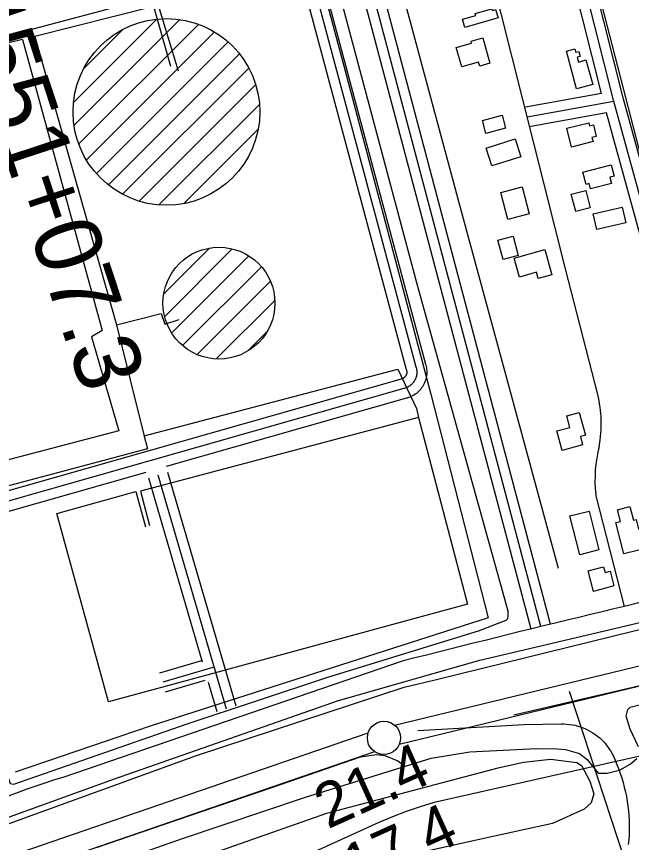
# Model space of a CAD drawing. Extents: x 3508733 to 3546731, y 546897 to 572481.
# Drawn here: x 3515132 to 3516057, y 565615 to 566859 of the extents above; entities that cross this region are included whole.
import ezdxf

# ---------------------------------------------------------------- set-up
doc = ezdxf.new("R2010")
doc.units = 0
for name, color, linetype in [('V-BLDG-OTLN', 7, 'Continuous'), ('V-DOMW-TANK', 7, 'Continuous'), ('V-FLOD-BASE', 7, 'Continuous'), ('V-LEVE-TOET', 7, 'Continuous'), ('V-RIVR-RANG', 7, 'Continuous'), ('V-ROAD-CNTR', 7, 'Continuous'), ('V-SITE-OTLN', 7, 'Continuous'), ('V-SITE-VEGE', 7, 'Continuous'), ('V-SURV-IDEN', 7, 'Continuous'), ('V-SURV-LINE', 7, 'Continuous'), ('V-TOPO-MINR', 7, 'Continuous'), ('V-TOPO-SHOR', 7, 'Continuous'), ('V-UTIL-LINE', 7, 'Continuous')]:
    doc.layers.add(name, color=color, linetype=linetype)

msp = doc.modelspace()

# ---------------------------------------------------------------- linework, layer by layer
at = {"layer": 'V-BLDG-OTLN'}
for points in [[(3515856, 566856.5), (3515806.2, 566842.1), (3515802.6, 566854.4), (3515822.5, 566860.2), (3515821.7, 566863), (3515846.5, 566870.2), (3515847.3, 566867.5), (3515852.4, 566869)], [(3515833, 566826.5), (3515843.8, 566788.4), (3515828.4, 566784), (3515826.7, 566790.1), (3515801.4, 566782.9), (3515793.1, 566812.1), (3515816.3, 566818.7), (3515815.5, 566821.5)], [(3515988.3, 566793.2), (3515998.4, 566756.3), (3515974.2, 566749.7), (3515958.8, 566806.3), (3515971.5, 566809.7), (3515972.9, 566804.7), (3515977.3, 566805.9), (3515979.3, 566798.4), (3515975, 566797.2), (3515976.9, 566790.1)], [(3515867.2, 566690.3), (3515837.8, 566682.6), (3515832.7, 566702.3), (3515862.1, 566709.9)], [(3515998.9, 566670.2), (3515966.3, 566662.1), (3515959.3, 566690.4), (3515992.6, 566698.6), (3515993.7, 566694.2), (3515999.5, 566695.6), (3516003.8, 566678), (3515997.3, 566676.4)], [(3515890.3, 566647.6), (3515846.7, 566633.6), (3515838.1, 566660.4), (3515881.6, 566674.4)], [(3515983.8, 566624.5), (3516026.2, 566635.4), (3516030.5, 566618.5), (3516024.1, 566616.8), (3516026.7, 566607), (3515995.2, 566599), (3515993.1, 566607), (3515988.6, 566605.9)], [(3515892.5, 566602), (3515902.9, 566561.5), (3515870.7, 566553.2), (3515860.3, 566593.6)], [(3515994.7, 566570.7), (3515972.8, 566565.1), (3515966.1, 566591), (3515988.1, 566596.7)], [(3516048.3, 566548.2), (3516004.8, 566538.1), (3515999.3, 566561.6), (3516042.9, 566571.7)], [(3515863.5, 566492.6), (3515855.7, 566522), (3515878.6, 566528.1), (3515886.4, 566498.7)], [(3515880.5, 566495), (3515926.5, 566507.8), (3515937.1, 566469.9), (3515916.5, 566464.1), (3515913.9, 566473.5), (3515888.5, 566466.4)], [(3515983.2, 566213.7), (3515952.6, 566205.3), (3515944.5, 566234.7), (3515964.2, 566240.1), (3515959.5, 566257.3), (3515978.1, 566262.4), (3515987.5, 566228.3), (3515979.8, 566226.2)], [(3515979.1, 566048.2), (3515964.2, 566106.7), (3515992.9, 566114), (3516007.8, 566055.5)], [(3516088.1, 566060.3), (3516045, 566049.5), (3516033.1, 566096.7), (3516040.1, 566098.4), (3516035.6, 566116.2), (3516054.5, 566121), (3516059.7, 566100.6), (3516063.8, 566101.6), (3516067.5, 566086.9), (3516080.6, 566090.2)], [(3516030.4, 566001.3), (3515999.8, 565993.2), (3515991.6, 566024.1), (3516014.8, 566030.3), (3516017.3, 566021.5), (3516024.6, 566023.4)]]:
    msp.add_lwpolyline(points, close=True, dxfattribs=at)
at = {"layer": 'V-DOMW-TANK'}
for p, q in [((3515217.7, 566729.7), (3515342.5, 566854.5)), ((3515218.3, 566695), (3515377.2, 566853.9)), ((3515225.5, 566666.8), (3515405.4, 566846.7)), ((3515233.3, 566780.7), (3515291.5, 566838.9)), ((3515236.8, 566642.7), (3515429.4, 566835.4)), ((3515251.8, 566622.4), (3515449.8, 566820.4)), ((3515269.8, 566605), (3515467.1, 566802.3)), ((3515291.3, 566591.2), (3515481, 566780.9)), ((3515316.2, 566580.8), (3515491.5, 566756)), ((3515345.7, 566574.9), (3515497, 566726.2)), ((3515383.2, 566577.1), (3515495.1, 566688.9)), ((3515353.5, 566441.2), (3515422, 566509.8)), ((3515354.6, 566407), (3515456.3, 566508.8)), ((3515365.2, 566382.3), (3515481.1, 566498.1)), ((3515381.6, 566363.3), (3515500.1, 566481.8)), ((3515403.5, 566349.8), (3515513.6, 566460)), ((3515432.1, 566343.1), (3515520, 566431)), ((3515479.6, 566355.2), (3515508.3, 566384))]:
    msp.add_line(p, q, dxfattribs=at)
for centre, radius in [((3515357.2, 566715), 140.5), ((3515436.2, 566427.1), 84.2)]:
    msp.add_circle(centre, radius, dxfattribs=at)
at = {"layer": 'V-FLOD-BASE'}
for points in [[(3515879.8, 565807.3), (3516153.3, 565871.3)], [(3515251.9, 565607.5), (3515370.1, 565648.2), (3515515.9, 565698), (3515649.3, 565744.1), (3515673.4, 565747.8), (3515685.8, 565746.1), (3515705.3, 565737.9), (3515710, 565734.4)]]:
    msp.add_lwpolyline(points, dxfattribs=at)
at = {"layer": 'V-LEVE-TOET'}
for points in [[(3514850.8, 565476.6), (3514903.4, 565510.7), (3515017.6, 565594.7), (3515041.7, 565614.3), (3515064, 565624.5), (3515103.4, 565637.7), (3515402.4, 565746.1), (3515714.9, 565848.8), (3515765.6, 565860.9), (3516060.6, 565934), (3516227.3, 565973.3), (3516431, 566026.4), (3516563, 566047.8)], [(3516067.1, 565759.4), (3516054.6, 565785.8), (3516048.6, 565805.2), (3516051.4, 565815.2), (3516055, 565818.8), (3516177.2, 565848.9)], [(3515263.9, 565580), (3515381.3, 565621.3), (3515566.3, 565683.5), (3515755.4, 565742.3), (3515813.5, 565751.5), (3515914.1, 565756.8), (3515945.3, 565756.4), (3515957.7, 565755.2), (3515978.3, 565748.9), (3515990.1, 565740.1), (3516006.7, 565719.6), (3516020.2, 565719.7), (3516038.1, 565724.2), (3516039.6, 565724.5), (3516054.9, 565732.9), (3516064.8, 565741.8)]]:
    msp.add_lwpolyline(points, dxfattribs=at)
at = {"layer": 'V-RIVR-RANG'}
msp.add_line((3515963.1, 565843.1), (3516255.8, 564949.8), dxfattribs=at)
at = {"layer": 'V-ROAD-CNTR'}
msp.add_line((3515735.5, 565783.6), (3515895.1, 565792.8), dxfattribs=at)
for points in [[(3516119.9, 566404), (3516029.5, 566732.6), (3515737.3, 567893)], [(3516134.4, 566407.9), (3516044, 566736.4), (3515751.8, 567896.6)], [(3516011.6, 566742.5), (3515722.7, 567889.3)], [(3515342.9, 567842.8), (3515468.4, 567376.2), (3515746.9, 566335.2)], [(3516006, 566289.8), (3515957.6, 566478.6), (3515637, 567752), (3515609.3, 567843.5)], [(3515328.4, 567838.9), (3515453.9, 567372.3), (3515732.4, 566331.3)], [(3515906, 565936.3), (3515404.9, 567828.5)], [(3515920.5, 565940.2), (3515419.4, 567832.3)], [(3515935, 565944), (3515433.9, 567836.2)], [(3515443.6, 567352.8), (3515718, 566327.4)], [(3516011.6, 566742.5), (3515897.4, 566722)], [(3516030.1, 566730.6), (3515900, 566707.3)], [(3516019.2, 566713.4), (3515902.7, 566692.5)], [(3516105.4, 566400), (3516019.2, 566713.4)], [(3515718.1, 566326.9), (3515718.4, 566325.9), (3515718.5, 566325.4), (3515718.6, 566324.8), (3515718.7, 566324.2), (3515718.8, 566323.6), (3515718.8, 566323), (3515718.7, 566322.5), (3515718.7, 566321.9), (3515718.6, 566321.3), (3515718.5, 566320.7), (3515718.3, 566320.2), (3515718.1, 566319.6), (3515717.9, 566319.1), (3515717.7, 566318.5), (3515717.4, 566318), (3515717.1, 566317.5), (3515716.8, 566317), (3515716.4, 566316.6), (3515716, 566316.1), (3515715.6, 566315.7), (3515715.2, 566315.3), (3515714.8, 566315), (3515714.3, 566314.6), (3515713.8, 566314.3), (3515713.3, 566314), (3515712.8, 566313.7), (3515712.2, 566313.5), (3515711.7, 566313.3), (3515711.1, 566313.1), (3515710.5, 566313)], [(3515732.4, 566331.3), (3515732.9, 566329.9), (3515733.2, 566328.5), (3515733.5, 566327.1), (3515733.6, 566325.7), (3515733.7, 566324.3), (3515733.8, 566322.9), (3515733.7, 566321.4), (3515733.6, 566320), (3515733.4, 566318.6), (3515733.1, 566317.2), (3515732.7, 566315.8), (3515732.3, 566314.5), (3515731.7, 566313.2), (3515731.1, 566311.9), (3515730.5, 566310.6), (3515729.7, 566309.4), (3515728.9, 566308.2), (3515728, 566307.1), (3515727.1, 566306), (3515726.1, 566305), (3515725.1, 566304), (3515724, 566303.1), (3515722.8, 566302.3), (3515721.6, 566301.5), (3515720.4, 566300.8), (3515719.1, 566300.1), (3515717.8, 566299.6), (3515716.5, 566299.1), (3515715.1, 566298.7), (3515714.2, 566298.4)], [(3515746.8, 566335.7), (3515747.3, 566333.9), (3515747.9, 566331.7), (3515748.3, 566329.5), (3515748.6, 566327.2), (3515748.7, 566325), (3515748.8, 566322.7), (3515748.7, 566320.4), (3515748.5, 566318.2), (3515748.1, 566315.9), (3515747.7, 566313.7), (3515747.1, 566311.5), (3515746.4, 566309.4), (3515745.5, 566307.3), (3515744.6, 566305.2), (3515743.5, 566303.2), (3515742.3, 566301.3), (3515741.1, 566299.4), (3515739.7, 566297.6), (3515738.2, 566295.9), (3515736.6, 566294.3), (3515734.9, 566292.7), (3515733.2, 566291.3), (3515731.4, 566289.9), (3515729.5, 566288.7), (3515727.5, 566287.6), (3515725.5, 566286.5), (3515723.4, 566285.6), (3515721.3, 566284.9), (3515719.2, 566284.2), (3515717.9, 566283.9)], [(3515710.1, 566312.9), (3514859.2, 566070.6), (3514514.1, 565975.8)], [(3515714.2, 566298.4), (3514863.3, 566056.1), (3514503.5, 565957.3), (3514615.1, 565518.5)], [(3515718.3, 566284), (3515356.8, 566181.1)], [(3515326.2, 566172.3), (3514885.1, 566046.8)], [(3515330.1, 566164.2), (3515411, 565887.3)], [(3515344.5, 566168.4), (3515447.2, 565816.5)], [(3515358.9, 566172.6), (3515461.6, 565820.7)], [(3516046.1, 565970.5), (3516003.1, 566139.1)], [(3515347.4, 565870.7), (3515410.3, 565889.2)], [(3515713.2, 565888.4), (3515201.1, 565712.9)], [(3515426.8, 565878.4), (3515351.7, 565856.3)], [(3515355.9, 565841.9), (3515415.6, 565859.4)], [(3515419.9, 565856.6), (3515432.8, 565812.3)], [(3515895.1, 565792.8), (3515951, 565793.7), (3515955.2, 565793.7), (3515959.4, 565793.5), (3515963.6, 565793), (3515967.8, 565792.4), (3515971.9, 565791.6), (3515975.9, 565790.5), (3515980, 565789.3), (3515983.9, 565787.8), (3515987.8, 565786.2), (3515991.6, 565784.4), (3515995.3, 565782.3), (3515998.8, 565780.1), (3516002.3, 565777.8), (3516005.7, 565775.2), (3516008.9, 565772.5), (3516012, 565769.7), (3516014.9, 565766.6), (3516017.7, 565763.5), (3516020.3, 565760.2), (3516022.7, 565756.8), (3516025, 565753.3), (3516027.1, 565749.6), (3516029, 565745.9), (3516032, 565739.3), (3516034.8, 565732.7), (3516038.1, 565724.2), (3516039.9, 565719.1), (3516042.1, 565712.3), (3516044.1, 565705.3), (3516045.9, 565698.4), (3516047.6, 565691.3), (3516049, 565684.3), (3516050.2, 565677.1), (3516051.2, 565670), (3516052, 565662.8), (3516052.6, 565655.6), (3516053, 565648.4), (3516053.2, 565641.2), (3516053.2, 565634), (3516053, 565626.8), (3516052.5, 565619.6), (3516051.9, 565612.4)]]:
    msp.add_lwpolyline(points, dxfattribs=at)
for centre, radius, start, end in [((3515817.4, 566245.2), 193.8, 350.0559, 13.3321), ((3516196.1, 566161.9), 194.3, 165.1624, 186.7292), ((3521341, 543799), 22795.1, 102.83341, 104.29325), ((3515450.5, 564860), 888.6, 106.2989, 120.8986)]:
    msp.add_arc(centre, radius, start, end, dxfattribs=at)
at = {"layer": 'V-SITE-OTLN'}
for p, q in [((3515507.4, 567218.7), (3515625.9, 566776.8)), ((3515625.9, 566776.8), (3515754.7, 566290.2)), ((3515754.7, 566290.2), (3515841.4, 565953.5)), ((3515841.4, 565953.5), (3515332.7, 565790.4)), ((3515332.7, 565790.4), (3515129.4, 565720.9))]:
    msp.add_line(p, q, dxfattribs=at)
at = {"layer": 'V-SITE-VEGE'}
msp.add_lwpolyline([(3515330.1, 565564.9), (3515598.7, 565659.4), (3515856.3, 565727.8), (3515894.1, 565736.3), (3515934.9, 565740.6), (3515974.6, 565735.6), (3515981.7, 565730.9), (3515994.3, 565707.3), (3516000.3, 565688.4), (3515996.3, 565674.7), (3515985.7, 565665.2), (3515937.9, 565643.6), (3515846.3, 565623.6), (3515748.8, 565602.3)], dxfattribs=at)
at = {"layer": 'V-SURV-LINE'}
for points in [[(3515700.3, 565791.9), (3518577.9, 566489.7)], [(3518584.9, 566460.5), (3515707.3, 565762.7)], [(3515124.2, 565595.4), (3515660.6, 565780.3)], [(3515670.4, 565751.9), (3515134, 565567)]]:
    msp.add_lwpolyline(points, dxfattribs=at)
msp.add_circle((3515684.4, 565772.6), 25, dxfattribs=at)
at = {"layer": 'V-TOPO-MINR'}
msp.add_lwpolyline([(3516546.1, 565852.6), (3515760.1, 565675.6), (3515738.8, 565669.1), (3515717.7, 565662), (3515697, 565653.9), (3515676.5, 565645.2), (3515198.1, 565427.2)], dxfattribs=at)
at = {"layer": 'V-TOPO-SHOR'}
for points in [[(3516447.8, 566401.5), (3516157.4, 566341.5), (3516153.9, 566339.7), (3516149.2, 566344.4), (3516075.7, 566630), (3515980.5, 566999.7), (3515908.1, 567307.1), (3515849, 567548.8)], [(3515947.2, 566027.5), (3515802.7, 566559.3), (3515583.5, 567374.1), (3515539.6, 567535.7)], [(3515871, 565963.5), (3515734.4, 566455.8), (3515490.5, 567368.8)], [(3514863.5, 565495.7), (3515050.9, 565627.1), (3515067.9, 565634.9), (3515279.2, 565711), (3515615.8, 565829.1), (3515828.4, 565889.9), (3516048, 565941.3), (3516248.3, 565989.7), (3516390.8, 566027.7), (3516503.2, 566052.5), (3516549.8, 566062.8)], [(3515062.5, 565880.4), (3515121.9, 565704), (3515127.8, 565702.8), (3515388.3, 565793.9), (3515600, 565864.1), (3515826.4, 565933.7), (3515868.2, 565949.9), (3515870.5, 565952.3), (3515871.1, 565956.4), (3515871, 565963.5)]]:
    msp.add_lwpolyline(points, dxfattribs=at)
at = {"layer": 'V-UTIL-LINE'}
for points in [[(3514891.3, 566880.6), (3514895, 566845.8), (3514876.8, 566839.8), (3514895.5, 566771.5), (3515026.8, 566804.1), (3515020.7, 566831.2), (3515033.7, 566834.2), (3515040.9, 566809.5), (3515291.2, 566875.8), (3515270.7, 566953), (3515237.7, 566944.5), (3515231, 566976.9)], [(3515287, 566980.2), (3515294.9, 566954.3), (3515279.6, 566948.9), (3515297.1, 566877), (3515341.2, 566887.9), (3515374.9, 566776.6)], [(3515363.7, 566783.1), (3515338.4, 566873.7), (3515159.3, 566828.5), (3515282.2, 566394.5), (3515349.3, 566411.4), (3515354.7, 566395.5), (3515376.5, 566402.7)], [(3515140.5, 566824.2), (3515260.4, 566386.1), (3515244.6, 566376.6), (3515285.5, 566234.7), (3514809.1, 566109.8), (3514615.9, 566057.4), (3514640.7, 565952.6), (3514578.3, 565929.2), (3514603.1, 565823.8), (3514566, 565815.3), (3514564.2, 565830.6), (3514555.1, 565865.4), (3514502.1, 565850.9), (3514495, 565847.9)], [(3515140.5, 566824.2), (3514897.9, 566765), (3514900.9, 566755), (3514949.7, 566768.3), (3514975.6, 566675.2)], [(3515282.2, 566394.5), (3515323.3, 566229), (3515328.7, 566207.8), (3515000.7, 566120.4), (3514635.6, 566016.8), (3514654.3, 565943.2), (3514585.5, 565923.9), (3514610.8, 565827.3), (3514618.4, 565829.8), (3514613, 565849.2), (3514640.1, 565853.5)], [(3515323.7, 566227.2), (3515705.3, 566327.9), (3515733.4, 566268.5), (3515736.4, 566255), (3515810, 565974.1), (3515360.7, 565851.7), (3515270, 565827), (3515192.3, 566110.3), (3515311.2, 566143.4), (3515325.7, 566090.4)], [(3515736.4, 566255), (3515318.3, 566144), (3515331.6, 566092.2)]]:
    msp.add_lwpolyline(points, dxfattribs=at)

# ---------------------------------------------------------------- texts
at = {"layer": 'V-RIVR-RANG'}
for s, p in [('21.4', (3515599.8, 565634.8)), ('17.4', (3515641.2, 565543.7))]:
    msp.add_text(s, height=67, rotation=24.2783, dxfattribs=at).set_placement(p)
at = {"layer": 'V-SURV-IDEN'}
msp.add_text('4551+07.3', height=100, rotation=288.2881, dxfattribs=at).set_placement((3515033.1, 566891.4))

doc.saveas('drawing.dxf')
